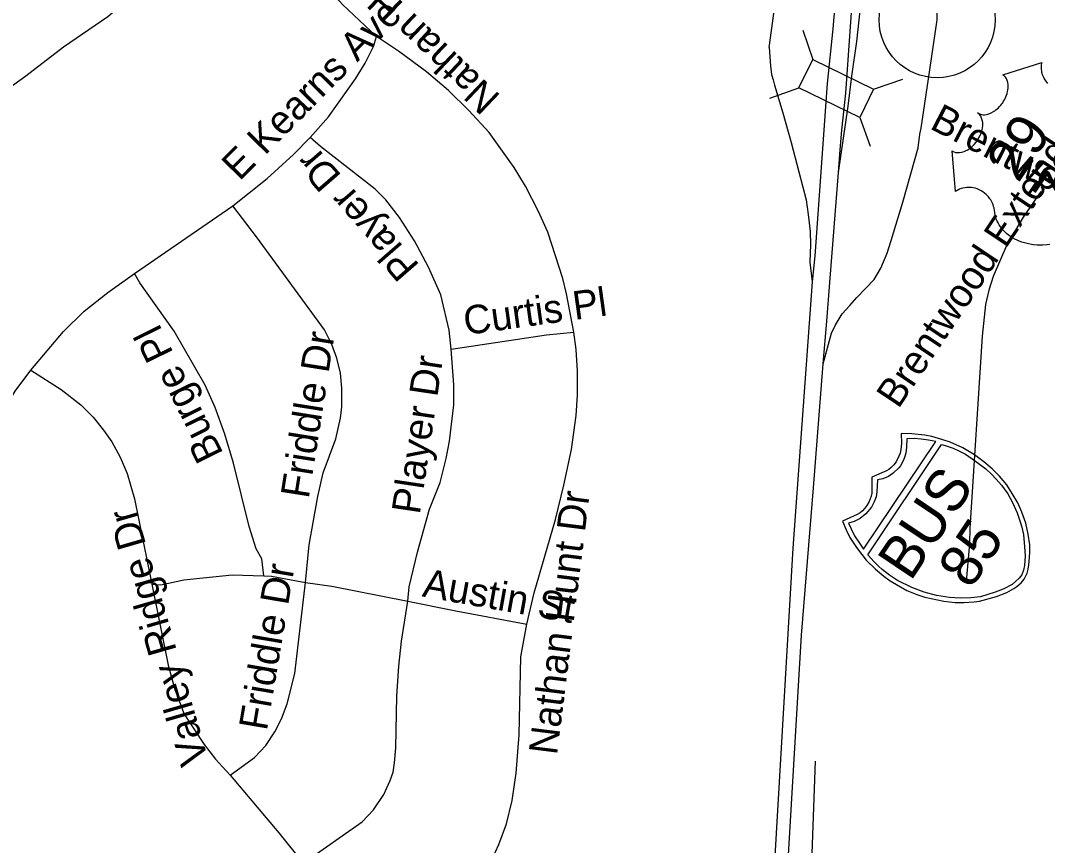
# Model space of a CAD drawing. Extents: x 1715610 to 1720914, y 798298 to 802505.
# Drawn here: x 1715831.7 to 1715906.1, y 799408.2 to 799467.9 of the extents above; entities that cross this region are included whole.
import ezdxf

# ---------------------------------------------------------------- set-up
doc = ezdxf.new("R2010")
doc.units = 0
doc.layers.add('Default', color=7, linetype='Continuous')
doc.layers.add('Prop DSN Text', color=7, linetype='Continuous')

msp = doc.modelspace()

# ---------------------------------------------------------------- linework, layer by layer
at = {"layer": 'Default'}
for p, q in [((1715888.348, 799467.204), (1715889.079, 799465.089)), ((1715885.963, 799462.298), (1715888.078, 799463.03)), ((1715893.482, 799462.936), (1715895.597, 799463.667)), ((1715892.486, 799460.887), (1715893.235, 799458.809)), ((1715839.954, 799449.598), (1715847.063, 799454.484))]:
    msp.add_line(p, q, dxfattribs=at)
for points in [[(1715891.466, 799462.649), (1715892.077, 799471.28), (1715892.177, 799473.558), (1715892.355, 799475.826), (1715892.388, 799477.939), (1715892.377, 799480.08), (1715892.42, 799481.732), (1715892.327, 799484.821), (1715892.147, 799487.042), (1715891.497, 799493.264), (1715890.354, 799498.654), (1715888.684, 799506.71), (1715887.791, 799510.779)], [(1715885.931, 799465.951), (1715886.498, 799470.203), (1715887.062, 799472.924), (1715887.29, 799475.837), (1715887.358, 799478.163), (1715886.995, 799483.689), (1715886.74, 799488.872), (1715886.322, 799492.554), (1715885.744, 799495.343), (1715884.889, 799498.05), (1715884.141, 799499.966)], [(1715890.929, 799456.896), (1715891.647, 799461.7), (1715891.908, 799463.889), (1715892.266, 799466.382), (1715893.685, 799479.619), (1715894.637, 799485.356), (1715895.176, 799490.35), (1715895.437, 799493.019)], [(1715896.919, 799460.107), (1715897.563, 799464.334), (1715898.084, 799467.966), (1715898.109, 799471.213), (1715897.659, 799475.177), (1715896.878, 799478.884), (1715896.205, 799481.564), (1715895.806, 799483.821), (1715895.578, 799485.176), (1715895.429, 799486.244), (1715895.431, 799487.264), (1715895.343, 799488.5), (1715895.388, 799489.779), (1715895.437, 799493.019)], [(1715857.476, 799466.768), (1715855.014, 799469.083), (1715854.177, 799470.03), (1715853.227, 799471.248), (1715852.552, 799472.344), (1715852.089, 799473.272), (1715851.554, 799474.546), (1715851.167, 799475.712), (1715850.547, 799478.564), (1715850.507, 799479.788)], [(1715891.107, 799479.013), (1715890.947, 799473.89), (1715890.674, 799468.99), (1715890.528, 799467.303), (1715890.123, 799463.34)], [(1715810.84, 799458.978), (1715811.375, 799458.677), (1715811.703, 799458.676), (1715813.16, 799459.261), (1715813.813, 799459.416), (1715814.389, 799459.476), (1715820.811, 799459.588), (1715822.649, 799459.8), (1715825.153, 799460.391), (1715827.649, 799461.275), (1715829.338, 799462.108), (1715830.773, 799462.976), (1715832.075, 799463.904), (1715834.817, 799466.011), (1715838.01, 799468.216), (1715839.014, 799469.048), (1715839.921, 799469.933), (1715841.27, 799471.569), (1715842.442, 799473.156)], [(1715852.683, 799459.432), (1715854, 799460.948), (1715855.954, 799463.694), (1715856.649, 799464.815), (1715857.253, 799466.034), (1715857.476, 799466.768)], [(1715871.773, 799445.342), (1715871.244, 799448.124), (1715870.982, 799449.232), (1715869.883, 799452.585), (1715869.215, 799454.082), (1715868.275, 799455.902), (1715867.451, 799457.268), (1715865.634, 799459.796), (1715864.166, 799461.397), (1715862.699, 799462.84), (1715861.094, 799464.189), (1715859.06, 799465.695), (1715857.476, 799466.768)], [(1715885.931, 799465.951), (1715886.015, 799464.622), (1715886.1, 799464.007), (1715886.203, 799463.624), (1715886.314, 799463.227), (1715886.906, 799461.218), (1715887.522, 799459.086), (1715888.077, 799456.941), (1715888.606, 799454.92), (1715888.753, 799453.854), (1715888.9, 799452.627), (1715888.924, 799451.697), (1715888.86, 799450.396), (1715889.043, 799448.983)], [(1715906.239, 799451.686), (1715906.046, 799451.661), (1715905.715, 799451.638), (1715905.485, 799451.636), (1715905.323, 799451.643), (1715905.068, 799451.666), (1715904.914, 799451.688), (1715904.695, 799451.729), (1715904.501, 799451.776), (1715904.321, 799451.827), (1715904.21, 799451.865), (1715904.021, 799451.939), (1715903.89, 799451.995), (1715903.715, 799452.08), (1715903.538, 799452.182), (1715903.381, 799452.284), (1715903.254, 799452.374), (1715903.113, 799452.49), (1715902.97, 799452.623), (1715902.853, 799452.745), (1715902.773, 799452.839), (1715902.68, 799452.96), (1715902.583, 799453.103), (1715902.499, 799453.252), (1715902.434, 799453.383), (1715902.371, 799453.535), (1715902.325, 799453.675), (1715902.284, 799453.844), (1715902.255, 799454.012), (1715902.241, 799454.156), (1715902.207, 799454.34), (1715902.18, 799454.442), (1715902.134, 799454.573), (1715902.086, 799454.686), (1715902.04, 799454.781), (1715901.967, 799454.915), (1715901.906, 799455.006), (1715901.806, 799455.137), (1715901.73, 799455.22), (1715901.629, 799455.321), (1715901.528, 799455.409), (1715901.395, 799455.507), (1715901.279, 799455.58), (1715901.136, 799455.654), (1715900.993, 799455.714), (1715900.861, 799455.758), (1715900.702, 799455.796), (1715900.58, 799455.814), (1715900.405, 799455.825), (1715900.233, 799455.821), (1715900.081, 799455.801), (1715899.939, 799455.773), (1715899.821, 799455.733), (1715899.713, 799455.693), (1715899.589, 799455.635), (1715899.479, 799455.572), (1715899.416, 799455.529), (1715899.171, 799458.474), (1715899.254, 799458.426), (1715899.361, 799458.382), (1715899.42, 799458.364), (1715899.543, 799458.346), (1715899.701, 799458.345), (1715899.877, 799458.374), (1715900.048, 799458.426), (1715900.149, 799458.469), (1715900.308, 799458.553), (1715900.469, 799458.66), (1715900.628, 799458.794), (1715900.775, 799458.94), (1715900.919, 799459.111), (1715901.045, 799459.292), (1715901.162, 799459.499), (1715901.266, 799459.745), (1715901.308, 799459.863), (1715901.344, 799460.001), (1715901.371, 799460.135), (1715901.386, 799460.29), (1715901.389, 799460.422), (1715901.385, 799460.529), (1715901.356, 799460.696), (1715901.309, 799460.845), (1715901.275, 799460.917), (1715901.24, 799460.983), (1715901.151, 799461.101), (1715901.108, 799461.146), (1715901.007, 799461.225), (1715901.101, 799461.172), (1715901.162, 799461.144), (1715901.227, 799461.122), (1715901.3, 799461.106), (1715901.409, 799461.093), (1715901.507, 799461.092), (1715901.666, 799461.11), (1715901.751, 799461.13), (1715901.824, 799461.152), (1715902.001, 799461.223), (1715902.18, 799461.324), (1715902.263, 799461.377), (1715902.342, 799461.436), (1715902.437, 799461.513), (1715902.528, 799461.598), (1715902.612, 799461.687), (1715902.695, 799461.779), (1715902.773, 799461.878), (1715902.832, 799461.962), (1715902.901, 799462.067), (1715902.96, 799462.167), (1715903.015, 799462.273), (1715903.069, 799462.395), (1715903.108, 799462.495), (1715903.155, 799462.631), (1715903.188, 799462.76), (1715903.209, 799462.879), (1715903.227, 799463.04), (1715903.231, 799463.177), (1715903.221, 799463.285), (1715903.2, 799463.421), (1715903.162, 799463.561), (1715903.126, 799463.653), (1715903.079, 799463.732), (1715903.026, 799463.811), (1715902.962, 799463.882), (1715902.901, 799463.936), (1715902.845, 799463.976), (1715905.661, 799464.872), (1715905.648, 799464.816), (1715905.629, 799464.677), (1715905.623, 799464.562), (1715905.627, 799464.367), (1715905.64, 799464.276), (1715905.656, 799464.184), (1715905.678, 799464.094), (1715905.7, 799464.012), (1715905.74, 799463.905), (1715905.784, 799463.803), (1715905.836, 799463.697), (1715905.886, 799463.612), (1715906.001, 799463.45), (1715906.08, 799463.356)], [(1715890.123, 799463.34), (1715889.223, 799450.869), (1715889.043, 799448.983)], [(1715890.929, 799456.896), (1715891.055, 799458.555), (1715891.182, 799459.975), (1715891.466, 799462.649)], [(1715889.827, 799443.034), (1715890.426, 799445.262), (1715890.699, 799445.832), (1715891.21, 799446.66), (1715891.767, 799447.267), (1715892.264, 799447.849), (1715893.518, 799449.159), (1715894.003, 799449.964), (1715894.463, 799451.053), (1715894.762, 799451.982), (1715895.597, 799454.756), (1715896.718, 799458.682), (1715896.844, 799459.673), (1715896.919, 799460.107)], [(1715847.063, 799454.484), (1715849.561, 799456.46), (1715851.456, 799458.215), (1715852.683, 799459.432)], [(1715862.876, 799444.107), (1715862.735, 799445.49), (1715862.136, 799448.05), (1715861.232, 799450.049), (1715860.232, 799451.948), (1715859.133, 799453.652), (1715858.142, 799454.934), (1715857.388, 799455.707), (1715853.429, 799458.782), (1715852.683, 799459.432)], [(1715889.827, 799443.034), (1715890.098, 799446.136), (1715890.309, 799448.926), (1715890.929, 799456.896)], [(1715905.59, 799455.522), (1715904.311, 799453.665), (1715903.144, 799451.672), (1715902.133, 799449.369), (1715901.826, 799448.371), (1715901.594, 799447.338), (1715901.342, 799445.04), (1715900.442, 799431.133), (1715900.429, 799430.036), (1715900.186, 799427.281)], [(1715852.337, 799427.213), (1715852.595, 799429.939), (1715853.239, 799433.437), (1715853.621, 799435.154), (1715854.522, 799437.6), (1715854.871, 799439.097), (1715854.961, 799439.93), (1715854.972, 799441.277), (1715854.877, 799442.377), (1715854.612, 799443.442), (1715854.252, 799444.451), (1715853.721, 799445.507), (1715848.781, 799452.248), (1715847.063, 799454.484)], [(1715832.443, 799442.576), (1715834.805, 799445.386), (1715836.292, 799446.857), (1715838.006, 799448.209), (1715839.954, 799449.598)], [(1715849.309, 799427.689), (1715849.167, 799428.909), (1715848.77, 799429.643), (1715848.262, 799431.252), (1715847.131, 799435.837), (1715846.499, 799437.948), (1715845.797, 799439.887), (1715845.064, 799441.5), (1715842.81, 799445.4), (1715840.335, 799448.908), (1715839.954, 799449.598)], [(1715889.043, 799448.983), (1715887.64, 799429.688), (1715886.301, 799406.954), (1715886.017, 799400.285), (1715885.861, 799393.898)], [(1715862.876, 799444.107), (1715869.782, 799445.138), (1715871.773, 799445.342)], [(1715868.36, 799424.19), (1715868.896, 799426.448), (1715870.432, 799431.761), (1715871.045, 799434.249), (1715871.592, 799436.83), (1715871.93, 799439.296), (1715872.035, 799440.764), (1715872.046, 799442.504), (1715871.934, 799444.083), (1715871.773, 799445.342)], [(1715859.748, 799425.845), (1715859.852, 799426.894), (1715860.444, 799429.39), (1715861.325, 799432.503), (1715862.095, 799434.455), (1715862.518, 799436.184), (1715862.754, 799437.449), (1715863.088, 799440.084), (1715863.084, 799441.514), (1715862.876, 799444.107)], [(1715886.497, 799391.997), (1715886.605, 799397.611), (1715887.281, 799406.656), (1715888.252, 799423.384), (1715889.127, 799434.064), (1715889.827, 799443.034)], [(1715826.615, 799426.007), (1715827.79, 799432.804), (1715828.716, 799435.858), (1715829.608, 799438.052), (1715830.218, 799439.23), (1715831.294, 799441.065), (1715832.443, 799442.576)], [(1715832.443, 799442.576), (1715834.639, 799441.188), (1715836.072, 799440.065), (1715836.944, 799439.171), (1715837.704, 799438.243), (1715838.295, 799437.384), (1715838.904, 799436.279), (1715839.415, 799435.093), (1715839.94, 799433.272), (1715841.216, 799427.079)], [(1715841.216, 799427.079), (1715841.863, 799427.039), (1715843.524, 799427.396), (1715847.012, 799427.767), (1715849.309, 799427.689)], [(1715849.309, 799427.689), (1715849.875, 799427.66), (1715852.337, 799427.213)], [(1715841.216, 799427.079), (1715842.391, 799421.209), (1715842.879, 799419.456), (1715843.555, 799417.656), (1715844.988, 799415.46), (1715845.823, 799414.401), (1715846.868, 799413.233)], [(1715846.868, 799413.233), (1715848.639, 799414.521), (1715849.457, 799415.397), (1715850.116, 799416.392), (1715850.602, 799417.336), (1715851.016, 799418.413), (1715851.552, 799420.6), (1715852.337, 799427.213)], [(1715852.337, 799427.213), (1715854.253, 799426.935), (1715859.748, 799425.845)], [(1715852.156, 799406.877), (1715856.449, 799409.863), (1715857.248, 799410.732), (1715858.014, 799411.852), (1715858.479, 799412.856), (1715858.688, 799413.455), (1715858.792, 799414.135), (1715858.867, 799415.233), (1715858.946, 799418.972), (1715859.091, 799421.149), (1715859.293, 799422.95), (1715859.748, 799425.845)], [(1715859.748, 799425.845), (1715863.217, 799425.139), (1715868.36, 799424.19)], [(1715858.049, 799399.877), (1715862.4, 799403.155), (1715863.113, 799403.748), (1715864.016, 799404.635), (1715865.232, 799406.144), (1715865.813, 799407.066), (1715866.346, 799408.228), (1715866.903, 799409.71), (1715867.309, 799411.415), (1715867.605, 799413.395), (1715867.806, 799416.159), (1715867.934, 799421.809), (1715868.36, 799424.19)], [(1715888.478, 799392.913), (1715888.447, 799394.676), (1715888.762, 799401.377), (1715889.039, 799407.558), (1715889.276, 799414.262)], [(1715846.868, 799413.233), (1715850.392, 799409.076), (1715852.156, 799406.877)]]:
    msp.add_lwpolyline(points, dxfattribs=at)
for points in [[(1715889.079, 799465.089), (1715893.487, 799462.946), (1715892.486, 799460.887), (1715888.078, 799463.03)], [(1715904.394, 799427.445), (1715904.492, 799427.628), (1715904.602, 799427.888), (1715904.678, 799428.161), (1715904.736, 799428.491), (1715904.779, 799429.008), (1715904.805, 799429.429), (1715904.804, 799429.936), (1715904.691, 799430.695), (1715904.511, 799431.497), (1715904.228, 799432.289), (1715903.924, 799432.969), (1715903.519, 799433.661), (1715903.123, 799434.278), (1715902.614, 799434.898), (1715902.08, 799435.44), (1715901.478, 799435.936), (1715900.792, 799436.458), (1715899.954, 799436.948), (1715899.037, 799437.36), (1715898.436, 799437.571), (1715897.69, 799437.782), (1715897.189, 799437.882), (1715896.242, 799437.97), (1715895.48, 799437.99), (1715895.498, 799437.265), (1715895.453, 799436.83), (1715895.41, 799436.575), (1715895.314, 799436.347), (1715895.111, 799435.947), (1715894.945, 799435.721), (1715894.752, 799435.538), (1715894.59, 799435.381), (1715894.416, 799435.281), (1715893.364, 799434.828), (1715893.346, 799433.681), (1715893.31, 799433.462), (1715893.231, 799433.266), (1715893.166, 799433.07), (1715892.997, 799432.788), (1715892.85, 799432.583), (1715892.668, 799432.394), (1715892.519, 799432.248), (1715892.3, 799432.12), (1715891.237, 799431.65), (1715891.488, 799431.019), (1715891.772, 799430.45), (1715892.236, 799429.738), (1715892.623, 799429.229), (1715892.954, 799428.829), (1715893.611, 799428.17), (1715894.22, 799427.65), (1715894.678, 799427.324), (1715895.902, 799426.629), (1715896.608, 799426.341), (1715897.197, 799426.135), (1715898.571, 799425.84), (1715899.396, 799425.758), (1715900.019, 799425.744), (1715900.771, 799425.805), (1715901.147, 799425.86), (1715902.397, 799426.196), (1715903.129, 799426.489), (1715903.651, 799426.765), (1715903.864, 799426.917), (1715904.166, 799427.175)], [(1715891.677, 799431.496), (1715891.85, 799431.093), (1715892.11, 799430.588), (1715892.415, 799430.118), (1715892.763, 799429.614), (1715897.986, 799437.413), (1715897.459, 799437.503), (1715896.922, 799437.58), (1715896.414, 799437.626), (1715895.889, 799437.619), (1715895.871, 799436.997), (1715895.809, 799436.578), (1715895.726, 799436.262), (1715895.629, 799436.013), (1715895.431, 799435.659), (1715895.321, 799435.514), (1715894.901, 799435.117), (1715894.56, 799434.886), (1715894.156, 799434.719), (1715893.762, 799434.629), (1715893.723, 799433.76), (1715893.66, 799433.406), (1715893.53, 799433.036), (1715893.342, 799432.662), (1715892.928, 799432.169), (1715892.505, 799431.848), (1715892.078, 799431.614)], [(1715898.402, 799437.201), (1715898.678, 799437.137), (1715899.244, 799436.925), (1715899.661, 799436.733), (1715900.136, 799436.505), (1715900.865, 799435.986), (1715901.611, 799435.435), (1715902.019, 799435.059), (1715902.37, 799434.687), (1715902.744, 799434.249), (1715903.216, 799433.632), (1715903.541, 799432.998), (1715903.876, 799432.253), (1715904.12, 799431.528), (1715904.216, 799431.219), (1715904.339, 799430.673), (1715904.417, 799429.778), (1715904.45, 799429.14), (1715904.41, 799428.43), (1715904.352, 799428.094), (1715904.214, 799427.751), (1715904.03, 799427.515), (1715903.75, 799427.267), (1715903.52, 799427.069), (1715902.877, 799426.73), (1715902.3, 799426.491), (1715901.229, 799426.167), (1715900.516, 799426.083), (1715899.742, 799426.076), (1715898.982, 799426.117), (1715898.034, 799426.252), (1715897.15, 799426.492), (1715896.253, 799426.836), (1715895.222, 799427.354), (1715894.633, 799427.728), (1715894.099, 799428.137), (1715893.843, 799428.385), (1715893.527, 799428.699), (1715893.063, 799429.216)]]:
    msp.add_lwpolyline(points, close=True, dxfattribs=at)
at = {"layer": 'Prop DSN Text'}
msp.add_circle((1715898.084, 799467.966), 4.2, dxfattribs=at)

# ---------------------------------------------------------------- texts
at = {"layer": 'Default'}
for s, height, rotation, p in [('Nathan Hunt Dr', 2.06625, 136.5008, (1715866.537, 799462.442)), ('E Kearns Ave', 2.06625, 45.31337, (1715847.551, 799456.232)), ('Brentwood Extended', 2.06625, 56.20506, (1715895.278, 799439.725)), ('Brentwood St', 2.06625, 332.62893, (1715897.473, 799460.122)), ('29', 2.9906, 56.20506, (1715903.957, 799456.08)), ('Player Dr', 2.0663, 131.02311, (1715860.656, 799450.172)), ('70', 2.9906, 56.20506, (1715907.327, 799453.767)), ('Curtis Pl', 2.0663, 7.89189, (1715863.926, 799445.124)), ('Burge Pl', 2.0663, 116.42851, (1715846.418, 799436.534)), ('Friddle Dr', 2.0663, 81.0064, (1715852.562, 799433.22)), ('Player Dr', 2.0663, 81.52202, (1715860.609, 799432.08)), ('BUS', 3.045, 56.20506, (1715896.154, 799427.217)), ('Nathan Hunt Dr', 2.06625, 82.87203, (1715870.549, 799414.655)), ('Valley Ridge Dr', 2.06625, 106.12958, (1715845.327, 799414.303)), ('85', 3.045, 56.20506, (1715900.513, 799426.639)), ('Friddle Dr', 2.0663, 80.39387, (1715849.531, 799416.409)), ('Austin St', 2.0663, 349.89143, (1715860.728, 799426.199))]:
    msp.add_text(s, height=height, rotation=rotation, dxfattribs=at).set_placement(p)

doc.saveas('drawing.dxf')
